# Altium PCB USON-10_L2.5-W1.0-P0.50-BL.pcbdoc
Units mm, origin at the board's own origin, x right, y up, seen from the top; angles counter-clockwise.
Board outline 15.35 x 14.5 mm, 2 copper layers (Top Layer, Bottom Layer), stack 0 mm thick; 1 components, 0 nets, 10 pads, 0 vias.
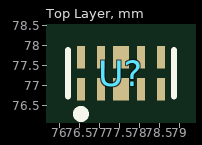
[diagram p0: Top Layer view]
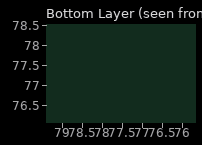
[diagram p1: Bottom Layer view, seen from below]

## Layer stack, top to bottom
Top Layer: signal copper (thickness not stored)
Bottom Layer: signal copper (thickness not stored)

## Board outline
85.202,69.85 69.85,69.85 69.85,84.352 85.202,84.352

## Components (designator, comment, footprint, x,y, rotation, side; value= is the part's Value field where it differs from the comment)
U? "" USON-10_L2.5-W1.0-P0.50-BL 77.526,77.319 r0 top

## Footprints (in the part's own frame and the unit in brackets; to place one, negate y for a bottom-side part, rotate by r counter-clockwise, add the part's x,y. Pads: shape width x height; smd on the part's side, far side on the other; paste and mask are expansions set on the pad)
USON-10_L2.5-W1.0-P0.50-BL [mm]
  rect 0.2x0.565 smd: 1(-1,-0.4) 2(-0.5,-0.4) 4(0.5,-0.4) 5(1,-0.4) 6(1,0.4) 7(0.5,0.4) 9(-0.5,0.4) 10(-1,0.4)
  rect 0.4x0.565 smd: 3(0,-0.4) 8(0,0.4)
  silkscreen extent -1.33,-1.12 1.33,0.58

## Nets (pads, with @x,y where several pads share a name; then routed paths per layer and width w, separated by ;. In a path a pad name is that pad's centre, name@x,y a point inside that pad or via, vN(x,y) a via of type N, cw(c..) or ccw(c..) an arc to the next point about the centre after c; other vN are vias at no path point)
pads on no net: U?.1 U?.2 U?.3 U?.4 U?.5 U?.6 U?.7 U?.8 U?.9 U?.10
